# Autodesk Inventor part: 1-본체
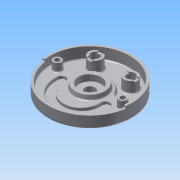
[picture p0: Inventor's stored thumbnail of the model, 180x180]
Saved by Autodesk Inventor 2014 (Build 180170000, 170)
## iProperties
Created: 2015-07
Part Number: 1-본체
Material: 알루미늄 6061
Document SubType Name: Modeling
Designer: Administrator
Density: 2.71 g/cm^3
Appearance: 알루미늄 - 평지
Mass: 1071 g
Surface Area: 1034.49 cm^2
Volume: 395.202 cm^3
Author: Administrator
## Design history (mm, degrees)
sketch "스케치1"
  geometry: C1 r 95 at (0, 0); 1 further point
  constraints: 1 centre point, 1 coincident
  dimensions: "d0" = 190 diameter of C1
extrude "돌출1" new body sketch "스케치1" distance "d1" = 32; taper "d2" = 0 deg
sketch "스케치2"
  geometry: C1 r 95 at (0, 0) reference; C2 r 90 at (0, 0)
  constraints: 1 centre point, 1 coincident
  dimensions: "d3" = 180 diameter of C2
extrude "돌출2" cut sketch "스케치2" distance "d4" = 18; taper "d5" = 0 deg
sketch "스케치3"
  geometry: L1 (45.033, 16)-(75.657, 16); L2 (-45.033, 16)-(-75.657, 16); A1 r 42 centre (0, 0) between (36.373, 21) and (-36.373, 21); A2 r 90 centre (0, 0) between (88.566, 16) and (-88.566, 16) reference; A3 r 90 centre (0, 0) between (85.114, 29.25) and (-85.114, 29.25); A4 r 10 centre (-75.657, 26) between (-85.114, 29.25) and (-75.657, 16); A5 r 10 centre (-45.033, 26) between (-45.033, 16) and (-36.373, 21); A6 r 10 centre (45.033, 26) between (36.373, 21) and (45.033, 16); A7 r 10 centre (75.657, 26) between (75.657, 16) and (85.114, 29.25); 3 further points
  constraints: 18 point on circle, 8 tangent, 6 centre point, 4 end point, 4 point on line, 3 equal radius, 2 coincident, 2 collinear, 1 horizontal
  dimensions: "d6" = 84 diameter of A1; "d8" = 16 distance from line of A3.centre L2; "d9" = 10 radius of A4
extrude "돌출3" cut sketch "스케치3" distance "d10" = 7; taper "d11" = 0 deg
sketch "스케치5"
  geometry: C1 r 35 at (0, 0); A1 r 90 centre (0, 0) between (-85.114, 29.25) and (85.114, 29.25) reference
  constraints: 1 centre point, 1 coincident
  dimensions: "d12" = 70 diameter of C1
extrude "돌출4" join sketch "스케치5" distance "d13" = 10; taper "d14" = -10 deg
sketch "스케치6"
  geometry: C1 r 15 at (-40, 52); C2 r 15 at (40, 52); A1 r 42 centre (0, 0) between (36.373, 21) and (-36.373, 21) reference
  constraints: 2 centre point, 1 equal radius, 1 horizontal alignment
  dimensions: "d15" = 80 distance of C2.centre C1.centre; "d16" = 30 diameter of C1; "d17" = 40 horizontal distance of A1.centre C1.centre; "d18" = 52 vertical distance of A1.centre C2.centre
extrude "돌출5" join sketch "스케치6" distance "d19" = 25; taper "d20" = 0 deg
sketch "스케치7"
  geometry: L1 (6, -21)-(-6, -21); L2 (-6, -21)-(-6, 21); L3 (-6, 21)-(6, 21); L4 (6, 21)-(6, -21); L5 (6, -21)-(-6, 21); L6 (-6, -21)-(6, 21); L7 (101, -6)-(59, -6); L8 (59, -6)-(59, 6); L9 (59, 6)-(101, 6); L10 (101, 6)-(101, -6); L11 (101, -6)-(59, 6); L12 (59, -6)-(101, 6); C1 r 15 at (0, 0) reference; C2 r 15 at (80, 0) reference; 1 further point
  constraints: 24 end point, 4 midpoint, 4 parallel, 4 perpendicular, 2 horizontal
  dimensions: "d21" = 12 distance of L2.end L3.end; "d22" = 42 distance of L3.end L1.start
extrude "돌출6" cut sketch "스케치7" distance "d23" = 3; taper "d24" = 0 deg
sketch "스케치8"
  geometry: C1 r 35 at (0, 0) reference; C2 r 9 at (-74, 0); C3 r 9 at (74, 0)
  constraints: 2 centre point, 2 horizontal alignment, 1 equal radius
  dimensions: "d25" = 18 diameter of C2; "d26" = 148 distance of C3.centre C2.centre; "d27" = 74 distance of C1.centre C2.centre
extrude "돌출7" join sketch "스케치8" distance "d28" = 18; taper "d29" = 0 deg
sketch "스케치9"
  geometry: L1 (-45.033, 16)-(-75.657, 16) reference; L2 (-59, -19)-(-59, -14); L3 (-41, -19)-(-41, -14); L4 (41, -19)-(41, -14); L5 (59, -19)-(59, -14); C1 r 35 at (0, 0) reference; A1 r 59 centre (0, -19) between (-59, -19) and (59, -19); A2 r 41 centre (0, -19) between (-41, -19) and (41, -19); A3 r 9 centre (-50, -14) between (-41, -14) and (-59, -14); A4 r 9 centre (50, -14) between (59, -14) and (41, -14)
  constraints: 8 end point, 8 point on circle, 8 tangent, 6 parallel, 4 centre point, 4 horizontal alignment, 1 perpendicular, 1 vertical alignment
  dimensions: "d30" = 19 distance of A1.centre C1.centre; "d31" = 59 radius of A1; "d32" = 41 radius of A2; "d33" = 5 distance of L5.start L5.end
extrude "돌출8" cut sketch "스케치9" distance "d34" = 7; taper "d35" = 0 deg
sketch "스케치10"
  geometry: C1 r 10 at (-40, 52); C2 r 10 at (40, 52); A1 r 15 centre (-40, 52) between (-46, 65.748) and (-46, 38.252) reference; A2 r 15 centre (40, 52) between (53.748, 58) and (26.252, 58) reference; 1 further point
  constraints: 2 centre point, 2 coincident, 1 equal radius
  dimensions: "d36" = 20 diameter of C1
extrude "돌출9" cut sketch "스케치10" stored distance "d37" = 7; taper "d38" = 0 deg
sketch "스케치11"
  geometry: C1 r 10 at (40, 52) reference; C2 r 10 at (-40, 52) reference; C3 r 95 at (0, 0) reference; C4 r 9 at (74, 0) reference; C5 r 9 at (-74, 0) reference; 2 further points
  constraints: 2 coincident
hole "구멍1" sketch "스케치11" at (-74, 0), (74, 0) diameter "d39" = 11; stored, may be unused: countersink angle "d43" = 90 deg, drill point angle "d45" = 118 deg; dims "d40" = 6, "d41" = 18, "d42" = 11, "d44" = 8
sketch "스케치12"
  geometry: C1 r 95 at (0, 0) reference; C2 r 68 at (0, 0)
  constraints: 1 centre point, 1 coincident, 1 other
  dimensions: "d55" = 136 diameter of C2
feature "엠보싱1" sketch "스케치12" dims "d56" = 0.5, "d57" = 0
sketch "스케치14"
  geometry: L1 (0, 0)-(94.075, -13.221); L2 (0, 0)-(-94.075, -13.221); C1 r 90 at (0, 0) reference; A1 r 95 centre (0, 0) between (94.075, -13.221) and (-94.075, -13.221) reference; 2 further points
  constraints: 4 end point, 4 point on circle, 2 horizontal alignment
  dimensions: "d61" = 8 deg dimension on C1.centre point (95, 0) L1.end; "d62" = 8 deg dimension on C1.centre point (-95, 0) L2.end
extrude "돌출10" cut sketch "스케치14" distance "d63" = 5; taper "d64" = 0 deg
sketch "스케치16"
  geometry: C1 r 95 at (0, 0) reference; C2 r 26 at (0, 0)
  constraints: 1 centre point, 1 coincident
  dimensions: "d71" = 52 diameter of C2
extrude "돌출12" join sketch "스케치16" distance "d72" = 12; taper "d73" = -15 deg
hole "구멍3" diameter "d76" = 23; stored, may be unused: countersink angle "d80" = 90 deg, drill point angle "d82" = 118 deg; dims "d74" = 10, "d75" = 10, "d77" = 6, "d78" = 50, "d79" = 15, "d81" = 8
chamfer "모따기2" distance "d83" = 1; stored, may be unused: second distance "d84" = 2, angle "d85" = 45 deg
fillet "모깎기1" dims "d86" = 1, "d87" = 0.3, "d88" = 5
fillet "모깎기2" dims "d89" = 3
fillet "모깎기3" dims "d90" = 3
node "솔리드1"
node "투영된 루프1"
node "투영된 루프2"
